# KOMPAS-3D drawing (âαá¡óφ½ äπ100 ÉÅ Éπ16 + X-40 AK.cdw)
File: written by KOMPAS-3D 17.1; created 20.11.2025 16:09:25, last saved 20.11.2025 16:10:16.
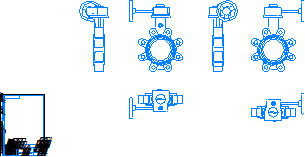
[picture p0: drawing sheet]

Sheet 1: A4, portrait

Title block, sheet 1: name: Гранвэл Ду100; material: Сталь 10  ГОСТ 1050-88; mass: 10,85; sheets: 1; sheet format: A4

Views: Вид 1, Спереди, Проекционный вид 2, Проекционный вид 4, Проекционный вид 5, Проекционный вид 6, Проекционный вид 7
Referenced files in \\adlc.lan\data\АДЛ_ПКД\3D-модели\ADL production\Дисковые поворотные затворы ГРАНВЭЛ\с резьбовыми проушинами с китайским редуктором Ру 16\KOMPAS 3D\: Гранвэл Ду100 РП Ру16 + X-40 AK.m3d
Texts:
  Andrey
  АДЛ
Dimensions and other numbers on the sheet: 1:1; 1; 10,85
